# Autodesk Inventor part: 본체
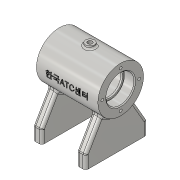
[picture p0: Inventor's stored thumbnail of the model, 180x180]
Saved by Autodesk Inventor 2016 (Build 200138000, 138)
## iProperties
Created: 2018-05
Part Number: 본체
Material: 알루미늄 6061
Document SubType Name: Modeling
Designer: Administrator
Density: 2.7 g/cm^3
Appearance: 알루미늄 - 평지
Mass: 317.68 g
Surface Area: 375.828 cm^2
Volume: 117.659 cm^3
Author: Administrator
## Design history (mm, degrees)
sketch "스케치1"
  geometry: L1 (-35, 0)-(35, 0); L2 (35, 26)-(-35, 26); L3 (-35, 26)-(-35, 16); L4 (-35, 16)-(-23, 16); L5 (-23, 16)-(-23, 14); L6 (-23, 14)-(-21, 14); L7 (-21, 14)-(-21, 21); L8 (-21, 21)-(21, 21); L9 (21, 21)-(21, 14); L10 (21, 14)-(23, 14); L11 (23, 14)-(23, 16); L12 (35, 26)-(35, 16); L13 (35, 16)-(23, 16); 1 further point
  constraints: 26 end point, 9 perpendicular, 3 point on line, 2 collinear, 2 vertical alignment, 1 horizontal, 1 midpoint, 1 parallel, 1 vertical
  dimensions: "d0" = 70 distance of L1.start L1.end; "d1" = 35 distance of L1.start point (0, 0); "d2" = 12 distance of L12.end L11.end; "d3" = 42 distance of L7.end L8.end; "d4" = 32 diameter of L13 L1; "d5" = 28 diameter of L10 L1; "d6" = 42 diameter of L8 L1; "d7" = 52 diameter of L2 L1
revolve "회전1" sketch "스케치1" stored, may be unused: angle "d8" = 90 deg
node "작업 평면2"
sketch "스케치3"
  geometry: C1 r 5 at (0, 0); 1 further point
  constraints: 1 centre point, 1 coincident
  dimensions: "d10" = 10 diameter of C1
extrude "돌출1" join sketch "스케치3" stored distance "d11" = 10; taper "d12" = 0 deg
node "작업 평면3"
sketch "스케치4"
  geometry: L1 (-19.386, 17.325)-(-50, 35); L2 (-50, 35)-(-65, 35); L3 (-65, 35)-(-65, -35); L4 (-65, -35)-(-50, -35); L5 (-50, -35)-(-19.386, -17.325); A1 r 26 centre (0, 0) between (-19.386, 17.325) and (-19.386, -17.325) reference; 1 further point
  constraints: 10 end point, 2 equal length, 2 perpendicular, 2 point on circle, 1 horizontal, 1 horizontal alignment, 1 midpoint
  dimensions: "d14" = 70 distance of L2.end L3.end; "d15" = 30 deg angle of L5 L4; "d17" = 65 distance from line of L3 A1.centre; "d76" = 15 distance of L1.end L2.end
extrude "돌출2" join sketch "스케치4" distance "d18" = 10; taper "d19" = 0 deg
sketch "스케치6"
  geometry: L1 (0, 0)-(26, 0); L2 (0, 0)-(-27.251, -9.919)
  constraints: 4 end point, 1 horizontal, 1 horizontal alignment, 1 other
  dimensions: "d20" = 29 distance of L1.start L2.end; "d21" = 20 deg angle of L1 L2
node "작업 평면4"
sketch "스케치7"
  geometry: C1 r 6 at (0, 0); 1 further point
  constraints: 1 centre point, 1 coincident
  dimensions: "d22" = 12 diameter of C1
extrude "돌출3" join sketch "스케치7" stored distance "d23" = 10; taper "d24" = 0 deg
hole "구멍1" diameter "d27" = 5.188; stored, may be unused: countersink angle "d31" = 90 deg, drill point angle "d33" = 118 deg; dims "d25" = 10, "d26" = 10, "d28" = 12, "d29" = 4, "d30" = 2, "d32" = 21.75
hole "구멍2" diameter "d36" = 5.188; stored, may be unused: countersink angle "d40" = 90 deg, drill point angle "d42" = 118 deg; dims "d34" = 10, "d35" = 10, "d37" = 12, "d38" = 4, "d39" = 2, "d41" = 21.75
sketch "스케치9"
  geometry: L1 (0, 70)-(10, 70) reference; L2 (0, 0)-(10, 0) reference; 4 further points
  constraints: 2 midpoint, 2 vertical alignment
  dimensions: "d43" = 15 distance of point (5, 70) point (5, 55); "d44" = 15 distance from line of L2 point (5, 15)
hole "구멍3" sketch "스케치9" at (5, 55), (5, 15) diameter "d45" = 4.134; stored, may be unused: countersink angle "d49" = 90 deg, drill point angle "d51" = 118 deg; dims "d46" = 8, "d47" = 4, "d48" = 2, "d50" = 10
sketch "스케치10" dims "d52" = 42
  geometry: C1 r 26 at (0, 0) reference; 2 further points
  constraints: 2 vertical alignment, 1 coincident, 2 other
hole "구멍4" sketch "스케치10" at (0, 21) diameter "d53" = 3.242; stored, may be unused: countersink angle "d57" = 90 deg, drill point angle "d59" = 118 deg; dims "d54" = 8, "d55" = 4, "d56" = 2, "d58" = 10
node "작업 평면5"
sketch "스케치11"
  geometry: L1 (-35, 26)-(35, 26) reference; L2 (-35, -26)-(-35, 26) reference; 1 further point
  constraints: 1 other
  dimensions: "d63" = 26 distance from line of point (0, 0) L1; "d64" = 35 distance from line of point (0, 0) L2
feature "엠보싱1" sketch "스케치11" dims "d0" = 70, "d1" = 35, "d2" = 12, "d3" = 42, "d4" = 32, "d5" = 28, "d6" = 42, "d7" = 52, "d65" = 0.5, "d66" = 0
fillet "모깎기1" dims "d67" = 2
fillet "모깎기2" dims "d68" = 3
fillet "모깎기3" dims "d69" = 3
fillet "모깎기4" dims "d70" = 3
fillet "모깎기5" dims "d71" = 0.3
chamfer "모따기1" distance "d72" = 1; stored, may be unused: second distance "d73" = 2, angle "d74" = 45 deg
fillet "모깎기6" dims "d75" = 3
node "솔리드1"
mirror "대칭1"
mirror "대칭2"
pattern_circular "원형 패턴1" dims angle "d61" = 360 deg
mirror "대칭3"
other parameters: "d9" = 29
